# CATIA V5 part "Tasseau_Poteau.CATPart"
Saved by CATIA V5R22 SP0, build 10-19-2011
Part number: Tasseau_Poteau
Bounding box of the stored display mesh (mm): x -36.5 to 36.5, y -31.5 to 31.5, z 0 to 420
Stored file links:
  U:\S9A\PER\CAO\Assemblage\Cadre\Poteau\Tasseau_Poteau.CATPart
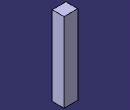
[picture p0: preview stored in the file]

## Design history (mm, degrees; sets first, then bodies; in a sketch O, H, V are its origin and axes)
Body1 (main body)
  Sketch1 on xy-plane, origin (0, 0, 0), H (1, 0, 0), V (0, 1, 0)
    point P1 (-36.5, 31.5)
    line L1 (-36.5, 31.5) -> (36.5, 31.5)
    line L2 (36.5, 31.5) -> (36.5, -31.5)
    line L3 (36.5, -31.5) -> (-36.5, -31.5)
    line L4 (-36.5, -31.5) -> (-36.5, 31.5)
    point P2 (36.5, 31.5)
    point P3 (36.5, -31.5)
    point P4 (-36.5, -31.5)
    length L2 = 63
    length L3 = 73
    horizontal: L1 H, L3 H
    vertical: L2 V, L4 V
    equidistance: P3 P1 O, P2 P4 O
  Pad1: profile Sketch1, direction (0, 0, 1), length 420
